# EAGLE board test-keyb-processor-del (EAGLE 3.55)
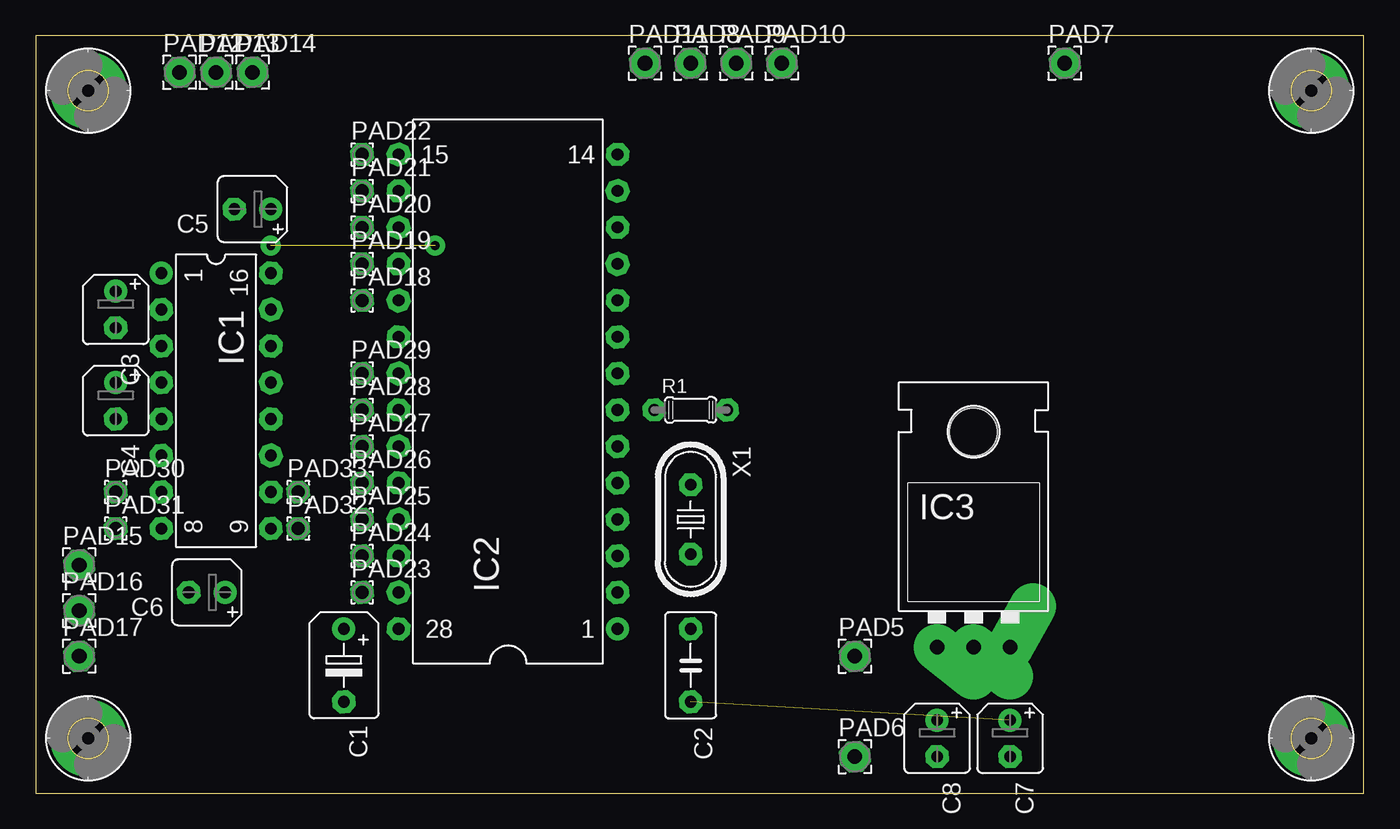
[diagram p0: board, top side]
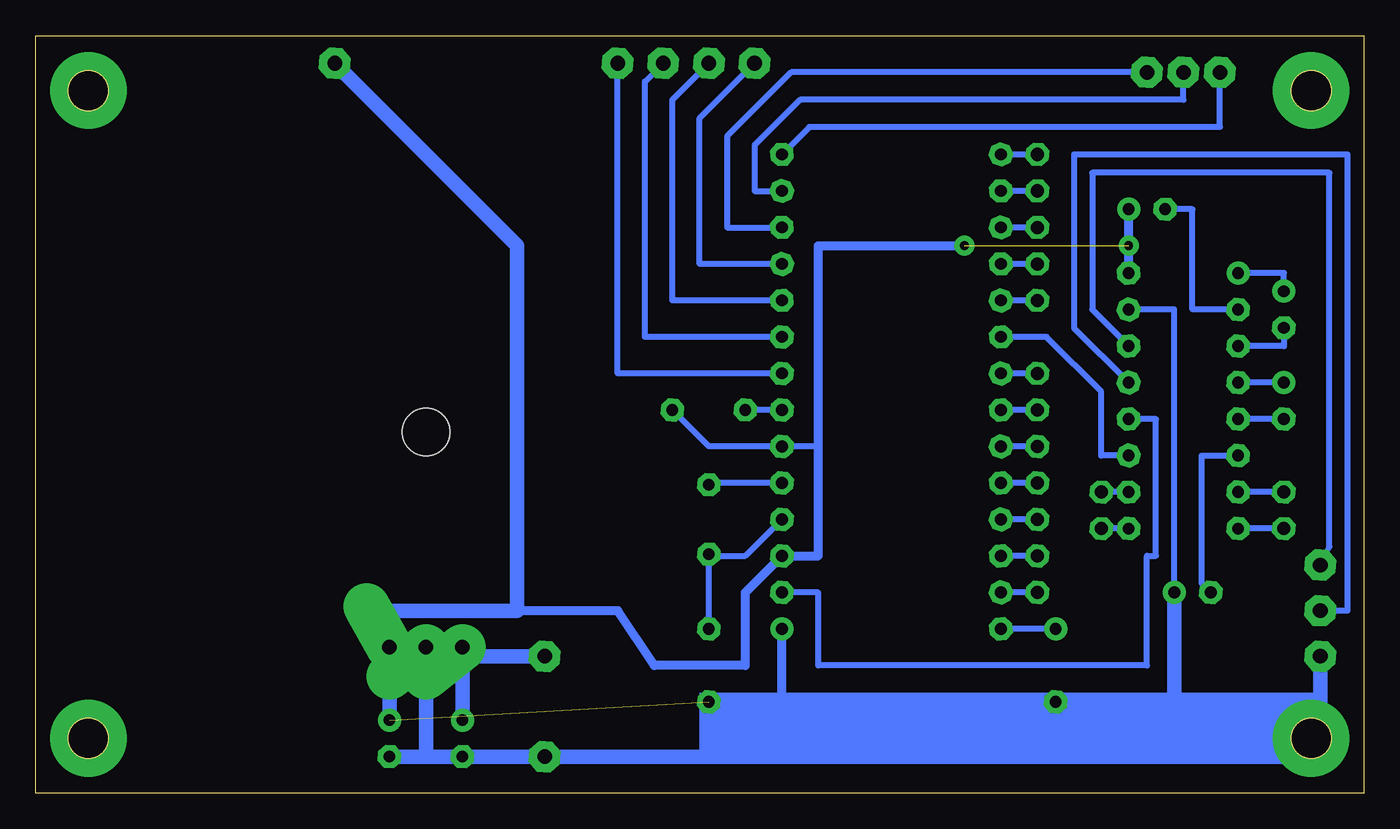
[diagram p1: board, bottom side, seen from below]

Size 92.38 x 52.7 mm. Coordinates in mm from the lower left corner, seen from the top.
Outline: 0,0 92.38,0 92.38,52.7 0,52.7 0,0
Copper layers used: Bottom

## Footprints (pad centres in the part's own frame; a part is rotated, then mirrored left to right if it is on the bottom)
5181B = drill 0.813 pad 1.6 round:  -2.54,0 | drill 0.813 pad 1.6 octagon:  2.54,0
B3,5 = drill 0.813 pad 1.6 octagon:  -2.54,0;  2.54,0
5181A = drill 0.813 pad 1.6 round:  -1.27,0 | drill 0.813 pad 1.6 octagon:  1.27,0
L16 = drill 0.813 pad 1.6 round:  -8.89,-3.81 | drill 0.813 pad 1.6 octagon:  -6.35,-3.81;  -3.81,-3.81;  -1.27,-3.81;  1.27,-3.81;  3.81,-3.81;  6.35,-3.81;  8.89,-3.81;  8.89,3.81;  6.35,3.81;  3.81,3.81;  1.27,3.81;  -1.27,3.81;  -3.81,3.81;  -6.35,3.81;  -8.89,3.81
L28 = drill 0.813 pad 1.6 round:  -16.51,-7.62 | drill 0.813 pad 1.6 octagon:  -13.97,-7.62;  -11.43,-7.62;  -8.89,-7.62;  -6.35,-7.62;  -3.81,-7.62;  -1.27,-7.62;  1.27,-7.62;  3.81,-7.62;  6.35,-7.62;  8.89,-7.62;  11.43,-7.62;  13.97,-7.62;  16.51,-7.62;  16.51,7.62;  13.97,7.62;  11.43,7.62;  8.89,7.62;  6.35,7.62;  3.81,7.62;  1.27,7.62;  -1.27,7.62;  -3.81,7.62;  -6.35,7.62;  -8.89,7.62;  -11.43,7.62;  -13.97,7.62;  -16.51,7.62
XXL = drill 1.016 pad 3.251 offset:  -2.54,-3.81;  0,-3.81;  2.54,-3.81 | hole 3.302: 0,11.176
2,8-P = drill 2.794 pad 5.334 round: 8 0,0
15/1,0 = drill 1.016 pad 2.159 octagon:  0,0
6/0,9 = drill 0.914 pad 1.6 octagon:  0,0
04/5 = drill 0.813 pad 1.6 octagon:  -2.54,0;  2.54,0
49U-V = drill 0.813 pad 1.6 octagon:  -2.413,0;  2.413,0

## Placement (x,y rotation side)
C1  1uF  [5181B]  21.42,8.88 270 top
C2  22pF  [B3,5]  45.55,8.88 270 top
C3  4.7uF  [5181A]  5.55,33.65 270 top
C4  4.7uF  [5181A]  5.55,27.3 270 top
C5  10uF  [5181A]  15.08,40.64 180 top
C6  10uF  [5181A]  11.9,13.96 180 top
C7  0.1uF  [5181A]  67.78,3.8 270 top
C8  0.1uF  [5181A]  62.7,3.8 270 top
IC1  MAX232  [L16]  12.54,27.3 270 top
IC2  68705P3  [L28]  32.86,27.93 90 top
IC3  78XXL  [XXL]  65.24,13.96 0 top
PAD1  BO2,8P  [2,8-P]  3.64,48.89 270 top
PAD2  BO2,8P  [2,8-P]  3.64,3.8 270 top
PAD3  BO2,8P  [2,8-P]  88.73,48.89 270 top
PAD4  BO2,8P  [2,8-P]  88.73,3.8 270 top
PAD5  2,15/1,0  [15/1,0]  56.98,9.52 0 top
PAD6  2,15/1,0  [15/1,0]  56.98,2.54 0 top
PAD7  2,15/1,0  [15/1,0]  71.59,50.8 0 top
PAD8  2,15/1,0  [15/1,0]  45.55,50.8 0 top
PAD9  2,15/1,0  [15/1,0]  48.73,50.8 0 top
PAD10  2,15/1,0  [15/1,0]  51.91,50.8 0 top
PAD11  2,15/1,0  [15/1,0]  42.38,50.8 0 top
PAD12  2,15/1,0  [15/1,0]  9.99,50.16 0 top
PAD13  2,15/1,0  [15/1,0]  12.54,50.16 0 top
PAD14  2,15/1,0  [15/1,0]  15.08,50.16 0 top
PAD15  2,15/1,0  [15/1,0]  3.01,15.87 0 top
PAD16  2,15/1,0  [15/1,0]  3.01,12.7 0 top
PAD17  2,15/1,0  [15/1,0]  3.01,9.52 0 top
PAD18  1,6/0,9  [6/0,9]  22.7,34.29 0 top
PAD19  1,6/0,9  [6/0,9]  22.7,36.83 0 top
PAD20  1,6/0,9  [6/0,9]  22.7,39.37 0 top
PAD21  1,6/0,9  [6/0,9]  22.7,41.91 0 top
PAD22  1,6/0,9  [6/0,9]  22.7,44.45 0 top
PAD23  1,6/0,9  [6/0,9]  22.7,13.96 0 top
PAD24  1,6/0,9  [6/0,9]  22.7,16.5 0 top
PAD25  1,6/0,9  [6/0,9]  22.7,19.04 0 top
PAD26  1,6/0,9  [6/0,9]  22.7,21.59 0 top
PAD27  1,6/0,9  [6/0,9]  22.7,24.12 0 top
PAD28  1,6/0,9  [6/0,9]  22.7,26.66 0 top
PAD29  1,6/0,9  [6/0,9]  22.7,29.2 0 top
PAD30  1,6/0,9  [6/0,9]  5.55,20.95 0 top
PAD31  1,6/0,9  [6/0,9]  5.55,18.41 0 top
PAD32  1,6/0,9  [6/0,9]  18.25,18.41 0 top
PAD33  1,6/0,9  [6/0,9]  18.25,20.95 0 top
R1  10K  [04/5]  45.55,26.66 0 top
X1  4MHz  [49U-V]  45.55,19.04 270 top

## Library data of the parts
C1 C3-C8 = cap-tant
C2 = cap
IC1 = maxim
IC2 = motorola
IC3 = v-reg
PAD1-PAD4 = holes
PAD5-PAD33 = wirepad
R1 = r
X1 = quartz

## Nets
N$1: IC2. PAD14.
N$2: IC2. PAD13.
N$3: IC2. PAD12.
N$4: IC1. IC2.
N$5: IC1. PAD15.
N$6: IC2. PAD11.
N$7: IC2. PAD8.
N$8: IC2. PAD9.
N$9: IC2. PAD10.
N$10: IC1. PAD16.
N$11: C2. IC2. X1.
N$12: IC2. X1.
N$13: C1. IC2.
N$14: IC1. IC2.
N$15: C3. IC1.
N$16: C3. IC1.
N$17: C4. IC1.
N$18: C4. IC1.
N$19: C5. IC1.
N$20: C6. IC1.
N$21: IC2. R1.
N$23: C8. IC3. PAD5.
N$24: IC2. PAD18.
N$25: IC2. PAD19.
N$26: IC2. PAD20.
N$27: IC2. PAD21.
N$28: IC2. PAD22.
N$29: IC2. PAD23.
N$30: IC2. PAD24.
N$31: IC2. PAD25.
N$32: IC2. PAD26.
N$33: IC2. PAD27.
N$34: IC2. PAD28.
N$35: IC2. PAD29.
N$36: IC1. PAD30.
N$37: IC1. PAD31.
N$38: IC1. PAD32.
N$39: IC1. PAD33.
VCC: C1. C2. C5. C6. C7. IC1. IC2. IC3. PAD7. PAD17. R1.
VDD: C7. C8. IC3. PAD6.

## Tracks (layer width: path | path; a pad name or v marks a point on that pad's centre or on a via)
N$1
  Bottom 0.406: 40.48,39.37 44.29,39.37 44.29,45.72 39.84,50.16 PAD14.
N$2
  Bottom 0.406: 40.48,41.91 42.38,41.91 42.38,45.08 39.2,48.26 12.54,48.26 PAD13.
N$3
  Bottom 0.406: 40.48,44.45 38.57,46.35 9.99,46.35 PAD12.
N$4
  Bottom 0.406: 16.34,23.49 18.25,23.49 18.25,27.93 22.06,31.75 25.23,31.75
N$5
  Bottom 0.406: PAD15. 2.38,17.14 2.38,43.18 18.88,43.18 18.88,33.65 16.34,31.11
N$6
  Bottom 0.406: 40.48,36.83 46.19,36.83 46.19,46.99 PAD11.
N$7
  Bottom 0.406: 40.48,34.29 48.09,34.29 48.09,48.26 PAD8.
N$8
  Bottom 0.406: 40.48,31.75 50,31.75 50,49.53 PAD9.
N$9
  Bottom 0.406: 40.48,29.2 51.91,29.2 PAD10.
N$10
  Bottom 0.406: 16.34,28.57 20.16,32.38 20.16,44.45 1.1,44.45 1.1,12.7 PAD16.
N$11
  Bottom 0.406: 40.48,19.04 43.02,16.5 45.55,16.5 X1. 45.55,11.43
N$12
  Bottom 0.406: 45.55,21.46 45.55,21.59 40.48,21.59
N$13
  Bottom 0.406: 21.42,11.43 IC2.
N$14
  Bottom 0.406: 16.34,26.03 14.44,26.03 14.44,16.5 15.08,16.5 15.08,8.88 37.94,8.88 37.94,13.96 40.48,13.96
N$15
  Bottom 0.406: 8.72,31.11 5.55,31.11 C3.
N$16
  Bottom 0.406: 5.55,34.92 5.55,36.19 8.72,36.19
N$17
  Bottom 0.406: 5.55,28.57 8.72,28.57
N$18
  Bottom 0.406: C4. 8.72,26.03
N$19
  Bottom 0.406: 8.72,33.65 11.9,33.65 11.9,40.64 C5.
N$20
  Bottom 0.406: 8.72,23.49 11.27,23.49 11.27,14.6 C6.
N$21
  Bottom 0.406: 40.48,26.66 43.02,26.66
N$22  (via drill 0.61 pad 1.4)
  other vias: 27.77,38.1
N$23
  Bottom 0.406: 62.7,9.52 62.7,10.15
  Bottom 1.016: 62.7,5.08 62.7,9.52 PAD5.
N$24
  Bottom 0.406: PAD18. 25.23,34.29
N$25
  Bottom 0.406: PAD19. 25.23,36.83
N$26
  Bottom 0.406: PAD20. 25.23,39.37
N$27
  Bottom 0.406: PAD21. 25.23,41.91
N$28
  Bottom 0.406: PAD22. 25.23,44.45
N$29
  Bottom 0.406: PAD23. 25.23,13.96
N$30
  Bottom 0.406: PAD24. 25.23,16.5
N$31
  Bottom 0.406: PAD25. 25.23,19.04
N$32
  Bottom 0.406: PAD26. 25.23,21.59
N$33
  Bottom 0.406: PAD27. 25.23,24.12
N$34
  Bottom 0.406: PAD28. 25.23,26.66
N$35
  Bottom 0.406: PAD29. 25.23,29.2
N$36
  Bottom 0.406: PAD30. 8.72,20.95
N$37
  Bottom 0.406: PAD31. 8.72,18.41
N$38
  Bottom 0.406: 16.34,18.41 PAD32.
N$39
  Bottom 0.406: 16.34,20.95 PAD33.
VCC  (via drill 0.61 pad 1.4)  (2 unrouted)
  Bottom 0.406: IC1. v16.34,38.1 | 37.94,24.12 40.48,24.12 45.55,24.12 R1. | 13.17,13.96 13.17,33.65 16.34,33.65 | C2. 40.48,6.35 C1. 13.17,6.35
  Bottom 0.61: 16.34,40.64 v16.34,38.1 IC1. | 27.77,38.1 37.94,38.1 37.94,24.12 37.94,16.5 40.48,16.5 43.02,13.96 43.02,8.88 49.37,8.88 51.91,12.7 58.89,12.7 | 40.48,6.35 40.48,11.43
  Bottom 1.016: PAD7. 58.89,38.1 58.89,12.7 67.78,12.7 IC3. 67.78,5.08 | 13.17,13.96 13.17,6.35 13.17,3.17 3.01,3.17 PAD17.
VDD
  Bottom 0.406: PAD6. C8.
  Bottom 1.016: 65.24,2.54 C8. PAD6. 3.01,2.54 | 65.24,2.54 C7. | 65.24,2.54 65.24,10.15
(copper drawn outside any net)
  shapes: Bottom area x5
